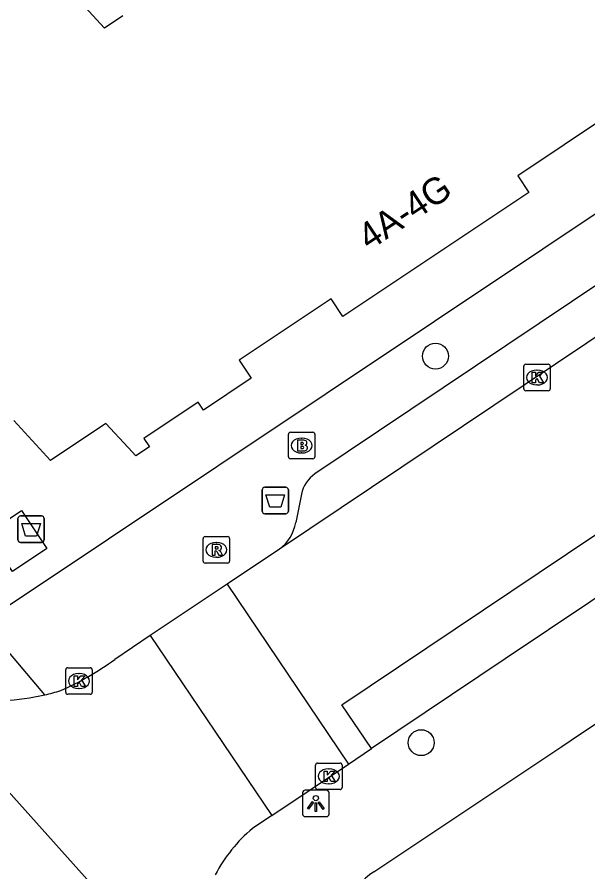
# Model space of a CAD drawing. Extents: x 161087 to 161922, y 382574 to 383873.
# Drawn here: x 161650.65 to 161672.22, y 382653.17 to 382685.44 of the extents above; entities that cross this region are included whole.
import ezdxf

# ---------------------------------------------------------------- set-up
doc = ezdxf.new("R2010")
doc.units = 0
for name, color, linetype in [('IMGEO_Afval_apart_plaats', 7, 'Continuous'), ('IMGEO_Afvalbak', 7, 'Continuous'), ('IMGEO_Boom', 7, 'Continuous'), ('IMGEO_Brandkraan', 7, 'Continuous'), ('IMGEO_Kolk', 7, 'Continuous'), ('IMGEO_Lichtpunt', 7, 'Continuous'), ('IMGEO_Pand', 7, 'Continuous'), ('IMGEO_Pand_nummerreeks', 7, 'Continuous'), ('IMGEO_Rijbaan_lokaal_gesloten', 7, 'Continuous'), ('IMGEO_Rijbaan_lokaal_open', 7, 'Continuous'), ('IMGEO_Rioolput', 7, 'Continuous'), ('IMGEO_Voetpad_gesloten', 7, 'Continuous'), ('IMGEO_Voetpad_open', 7, 'Continuous')]:
    doc.layers.add(name, color=color, linetype=linetype)

msp = doc.modelspace()

# ---------------------------------------------------------------- linework, layer by layer
at = {"layer": 'IMGEO_Afval_apart_plaats'}
for p, q in [((161650.686, 382665.711), (161650.686, 382666.511)), ((161650.686, 382666.511), (161650.686, 382665.711)), ((161650.786, 382666.611), (161651.576, 382666.611)), ((161651.576, 382666.611), (161650.786, 382666.611)), ((161651.676, 382666.511), (161651.676, 382665.711)), ((161651.676, 382665.711), (161651.676, 382666.511)), ((161651.576, 382665.611), (161650.786, 382665.611)), ((161650.786, 382665.611), (161651.576, 382665.611))]:
    msp.add_line(p, q, dxfattribs=at)
msp.add_lwpolyline([(161650.829, 382666.325), (161651.533, 382666.325), (161651.384, 382665.855), (161650.978, 382665.855), (161650.829, 382666.325)], dxfattribs=at)
for centre, start, end in [((161650.786, 382666.511), 90, 180), ((161650.786, 382666.511), 90, 180), ((161651.576, 382666.511), 0, 90), ((161651.576, 382666.511), 360, 90), ((161650.786, 382665.711), 180, 270), ((161650.786, 382665.711), 180, 270), ((161651.576, 382665.711), 270, 0), ((161651.576, 382665.711), 270, 0)]:
    msp.add_arc(centre, 0.1, start, end, dxfattribs=at)
at = {"layer": 'IMGEO_Afvalbak'}
for p, q in [((161659.915, 382666.795), (161659.915, 382667.595)), ((161659.915, 382667.595), (161659.915, 382666.795)), ((161660.015, 382667.695), (161660.805, 382667.695)), ((161660.805, 382667.695), (161660.015, 382667.695)), ((161660.905, 382667.595), (161660.905, 382666.795)), ((161660.905, 382666.795), (161660.905, 382667.595)), ((161660.805, 382666.695), (161660.015, 382666.695)), ((161660.015, 382666.695), (161660.805, 382666.695))]:
    msp.add_line(p, q, dxfattribs=at)
msp.add_lwpolyline([(161660.058, 382667.409), (161660.762, 382667.409), (161660.613, 382666.939), (161660.207, 382666.939), (161660.058, 382667.409)], dxfattribs=at)
for centre, start, end in [((161660.015, 382667.595), 90, 180), ((161660.015, 382667.595), 90, 180), ((161660.805, 382667.595), 0, 90), ((161660.805, 382667.595), 360, 90), ((161660.015, 382666.795), 180, 270), ((161660.015, 382666.795), 180, 270), ((161660.805, 382666.795), 270, 0), ((161660.805, 382666.795), 270, 0)]:
    msp.add_arc(centre, 0.1, start, end, dxfattribs=at)
at = {"layer": 'IMGEO_Boom'}
for centre in [(161666.46, 382672.645), (161665.922, 382658.053)]:
    msp.add_circle(centre, 0.489, dxfattribs=at)
at = {"layer": 'IMGEO_Brandkraan'}
for p, q in [((161660.98, 382669.77), (161661.832, 382669.77)), ((161660.905, 382668.844), (161660.905, 382669.696)), ((161661.393, 382669.55), (161661.418, 382669.55)), ((161661.906, 382669.696), (161661.906, 382668.844)), ((161661.832, 382668.77), (161660.98, 382668.77)), ((161661.416, 382668.99), (161661.391, 382668.99))]:
    msp.add_line(p, q, dxfattribs=at)
for points in [[(161660.98, 382669.77), (161661.832, 382669.77)], [(161660.905, 382668.844), (161660.905, 382669.696)], [(161661.253, 382669.47), (161661.253, 382669.07), (161661.466, 382669.07)], [(161661.484, 382669.47), (161661.253, 382669.47)], [(161661.906, 382669.696), (161661.906, 382668.844)], [(161661.432, 382669.389), (161661.378, 382669.389), (161661.378, 382669.313)], [(161661.378, 382669.313), (161661.431, 382669.313)], [(161661.44, 382669.237), (161661.378, 382669.237), (161661.378, 382669.156)], [(161661.378, 382669.156), (161661.44, 382669.156)], [(161661.832, 382668.77), (161660.98, 382668.77)]]:
    msp.add_lwpolyline(points, dxfattribs=at)
for centre, radius, start, end in [((161660.982, 382669.694), 0.0765, 91.552, 178.448), ((161660.982, 382669.694), 0.0765, 91.552, 178.448), ((161661.83, 382669.694), 0.0765, 1.552, 88.448), ((161661.83, 382669.694), 0.0765, 1.552, 88.448), ((161661.488, 382669.325), 0.145, 59.4692, 91.5367), ((161661.513, 382669.372), 0.0922, 285.5137, 58.1501), ((161661.433, 382669.351), 0.0379, 267.8285, 90.9355), ((161661.441, 382669.196), 0.0404, 269.8759, 90.5077), ((161661.518, 382669.18), 0.105, 301.3115, 78.989), ((161660.982, 382668.846), 0.0765, 181.552, 268.448), ((161660.982, 382668.846), 0.0765, 181.552, 268.448), ((161661.472, 382669.321), 0.251, 268.6676, 293.5347), ((161661.83, 382668.846), 0.0765, 271.552, 358.448), ((161661.83, 382668.846), 0.0765, 271.552, 358.448)]:
    msp.add_arc(centre, radius, start, end, dxfattribs=at)
for centre, major_axis, ratio, start_param, end_param in [((161661.392, 382669.27), (-0.387, 0.002), 0.722429, 4.712389, 7.853982), ((161661.417, 382669.27), (-0.39, 0.002), 0.717154, 1.570796, 4.712389)]:
    msp.add_ellipse(centre, major_axis=major_axis, ratio=ratio, start_param=start_param, end_param=end_param, dxfattribs=at)
at = {"layer": 'IMGEO_Kolk'}
for p, q in [((161669.871, 382672.338), (161670.723, 382672.338)), ((161669.796, 382671.412), (161669.796, 382672.264)), ((161670.284, 382672.118), (161670.309, 382672.118)), ((161670.797, 382672.264), (161670.797, 382671.412)), ((161670.307, 382671.558), (161670.282, 382671.558)), ((161670.723, 382671.338), (161669.871, 382671.338)), ((161652.491, 382659.954), (161652.491, 382660.806)), ((161652.566, 382660.88), (161653.418, 382660.88)), ((161653.492, 382660.806), (161653.492, 382659.954)), ((161652.979, 382660.66), (161653.004, 382660.66)), ((161653.002, 382660.1), (161652.977, 382660.1)), ((161653.418, 382659.88), (161652.566, 382659.88)), ((161661.929, 382656.357), (161661.929, 382657.209)), ((161662.004, 382657.283), (161662.856, 382657.283)), ((161662.93, 382657.209), (161662.93, 382656.357)), ((161662.417, 382657.063), (161662.442, 382657.063)), ((161662.856, 382656.283), (161662.004, 382656.283)), ((161662.44, 382656.503), (161662.415, 382656.503))]:
    msp.add_line(p, q, dxfattribs=at)
for points in [[(161669.871, 382672.338), (161670.723, 382672.338)], [(161669.796, 382671.412), (161669.796, 382672.264)], [(161670.117, 382672.038), (161670.24, 382672.038), (161670.24, 382671.887), (161670.37, 382672.038), (161670.534, 382672.038), (161670.388, 382671.887), (161670.541, 382671.638), (161670.389, 382671.638), (161670.304, 382671.802), (161670.24, 382671.735), (161670.24, 382671.638), (161670.117, 382671.638), (161670.117, 382672.038)], [(161670.797, 382672.264), (161670.797, 382671.412)], [(161670.723, 382671.338), (161669.871, 382671.338)], [(161652.491, 382659.954), (161652.491, 382660.806)], [(161652.566, 382660.88), (161653.418, 382660.88)], [(161653.492, 382660.806), (161653.492, 382659.954)], [(161652.812, 382660.58), (161652.935, 382660.58), (161652.935, 382660.429), (161653.065, 382660.58), (161653.229, 382660.58), (161653.083, 382660.429), (161653.236, 382660.18), (161653.084, 382660.18), (161652.999, 382660.344), (161652.935, 382660.277), (161652.935, 382660.18), (161652.812, 382660.18), (161652.812, 382660.58)], [(161653.418, 382659.88), (161652.566, 382659.88)], [(161661.929, 382656.357), (161661.929, 382657.209)], [(161662.004, 382657.283), (161662.856, 382657.283)], [(161662.93, 382657.209), (161662.93, 382656.357)], [(161662.25, 382656.983), (161662.373, 382656.983), (161662.373, 382656.832), (161662.503, 382656.983), (161662.667, 382656.983), (161662.521, 382656.832), (161662.674, 382656.583), (161662.522, 382656.583), (161662.437, 382656.747), (161662.373, 382656.68), (161662.373, 382656.583), (161662.25, 382656.583), (161662.25, 382656.983)], [(161662.856, 382656.283), (161662.004, 382656.283)]]:
    msp.add_lwpolyline(points, dxfattribs=at)
for centre, start, end in [((161669.873, 382672.262), 91.552, 178.448), ((161669.873, 382672.262), 91.552, 178.448), ((161670.721, 382672.262), 1.552, 88.448), ((161670.721, 382672.262), 1.552, 88.448), ((161669.873, 382671.414), 181.552, 268.448), ((161669.873, 382671.414), 181.552, 268.448), ((161670.721, 382671.414), 271.552, 358.448), ((161670.721, 382671.414), 271.552, 358.448), ((161652.568, 382660.804), 91.552, 178.448), ((161652.568, 382660.804), 91.552, 178.448), ((161653.416, 382660.804), 1.552, 88.448), ((161653.416, 382660.804), 1.552, 88.448), ((161652.568, 382659.956), 181.552, 268.448), ((161652.568, 382659.956), 181.552, 268.448), ((161653.416, 382659.956), 271.552, 358.448), ((161653.416, 382659.956), 271.552, 358.448), ((161662.006, 382657.207), 91.552, 178.448), ((161662.006, 382657.207), 91.552, 178.448), ((161662.854, 382657.207), 1.552, 88.448), ((161662.854, 382657.207), 1.552, 88.448), ((161662.006, 382656.359), 181.552, 268.448), ((161662.006, 382656.359), 181.552, 268.448), ((161662.854, 382656.359), 271.552, 358.448), ((161662.854, 382656.359), 271.552, 358.448)]:
    msp.add_arc(centre, 0.0765, start, end, dxfattribs=at)
for centre, major_axis, ratio, start_param, end_param in [((161670.283, 382671.838), (-0.387, 0.002), 0.722429, 4.712389, 7.853982), ((161670.308, 382671.838), (-0.39, 0.002), 0.717154, 1.570796, 4.712389), ((161652.978, 382660.38), (-0.387, 0.002), 0.722429, 4.712389, 7.853982), ((161653.003, 382660.38), (-0.39, 0.002), 0.717154, 1.570796, 4.712389), ((161662.416, 382656.783), (-0.387, 0.002), 0.722429, 4.712389, 7.853982), ((161662.441, 382656.783), (-0.39, 0.002), 0.717154, 1.570796, 4.712389)]:
    msp.add_ellipse(centre, major_axis=major_axis, ratio=ratio, start_param=start_param, end_param=end_param, dxfattribs=at)
at = {"layer": 'IMGEO_Lichtpunt'}
for p, q in [((161662.345, 382656.258), (161661.537, 382656.258)), ((161662.345, 382656.258), (161661.537, 382656.258)), ((161661.443, 382656.163), (161661.443, 382655.356)), ((161661.443, 382656.163), (161661.443, 382655.356)), ((161662.439, 382655.356), (161662.439, 382656.163)), ((161662.439, 382655.356), (161662.439, 382656.163)), ((161661.537, 382655.262), (161662.345, 382655.262)), ((161661.537, 382655.262), (161662.345, 382655.262))]:
    msp.add_line(p, q, dxfattribs=at)
for points in [[(161661.817, 382655.827), (161661.856, 382655.799), (161661.668, 382655.537), (161661.63, 382655.564), (161661.817, 382655.827)], [(161661.919, 382655.779), (161661.966, 382655.779), (161661.966, 382655.457), (161661.919, 382655.457), (161661.919, 382655.779)], [(161662.029, 382655.799), (161662.067, 382655.826), (161662.254, 382655.564), (161662.215, 382655.536), (161662.029, 382655.799)]]:
    msp.add_lwpolyline(points, dxfattribs=at)
msp.add_circle((161661.942, 382655.961), 0.0994, dxfattribs=at)
for centre, start, end in [((161661.537, 382656.163), 90, 180), ((161661.537, 382656.163), 90, 180), ((161662.345, 382656.163), 0, 90), ((161662.345, 382656.163), 0, 90), ((161661.537, 382655.356), 180, 270), ((161661.537, 382655.356), 180, 270), ((161662.345, 382655.356), 270, 0), ((161662.345, 382655.356), 270, 360)]:
    msp.add_arc(centre, 0.0946, start, end, dxfattribs=at)
at = {"layer": 'IMGEO_Pand'}
for points in [[(161654.648, 382685.492), (161653.956, 382685.031), (161647.175, 382692.39)], [(161680.47, 382685.832), (161673.485, 382681.175), (161673.077, 382681.786), (161669.572, 382679.45), (161669.988, 382678.826), (161662.965, 382674.144), (161662.524, 382674.806), (161659.048, 382672.489), (161659.499, 382671.812), (161657.692, 382670.607), (161657.496, 382670.901), (161655.445, 382669.534), (161655.654, 382669.221), (161655.143, 382668.881), (161654.854, 382669.193), (161654.012, 382670.104), (161651.92, 382668.71), (161650.536, 382670.209)]]:
    msp.add_lwpolyline(points, dxfattribs=at)
at = {"layer": 'IMGEO_Rijbaan_lokaal_gesloten'}
msp.add_lwpolyline([(161658.558, 382647.024), (161645.804, 382661.238)], dxfattribs=at)
at = {"layer": 'IMGEO_Rijbaan_lokaal_open'}
for points in [[(161699.988, 382691.772), (161660.57, 382665.356)], [(161664.046, 382657.83), (161662.924, 382659.486), (161675.735, 382668.065), (161680.939, 382671.625), (161685.938, 382675.035), (161686.973, 382675.729), (161688.094, 382674.073)], [(161660.57, 382665.356), (161658.586, 382664.031)], [(161658.586, 382664.031), (161655.686, 382662.094)], [(161658.586, 382664.031), (161663.174, 382657.246)], [(161655.686, 382662.094), (161654.342, 382661.196)], [(161655.686, 382662.094), (161660.282, 382655.309)], [(161663.174, 382657.246), (161664.046, 382657.83)], [(161660.282, 382655.309), (161663.174, 382657.246)], [(161660.282, 382655.309), (161659.549, 382654.818)]]:
    msp.add_lwpolyline(points, dxfattribs=at)
for centre, radius, start, end in [((161647.618, 382670.467), 11.453, 294.1911, 305.9528), ((161649.675, 382668.799), 9.166, 263.1686, 282.7798), ((161649.537, 382669.325), 9.71, 282.8883, 286.5988), ((161663.299, 382650.358), 5.827, 130.057, 152.2727)]:
    msp.add_arc(centre, radius, start, end, dxfattribs=at)
at = {"layer": 'IMGEO_Rioolput'}
for p, q in [((161657.682, 382664.906), (161657.682, 382665.758)), ((161657.757, 382665.832), (161658.609, 382665.832)), ((161658.17, 382665.612), (161658.195, 382665.612)), ((161658.683, 382665.758), (161658.683, 382664.906)), ((161658.193, 382665.052), (161658.168, 382665.052)), ((161658.609, 382664.832), (161657.757, 382664.832))]:
    msp.add_line(p, q, dxfattribs=at)
for points in [[(161657.682, 382664.906), (161657.682, 382665.758)], [(161657.757, 382665.832), (161658.609, 382665.832)], [(161658.683, 382665.758), (161658.683, 382664.906)], [(161658.271, 382665.53), (161658.019, 382665.532), (161658.019, 382665.132)], [(161658.019, 382665.132), (161658.143, 382665.132), (161658.143, 382665.294), (161658.154, 382665.294)], [(161658.197, 382665.451), (161658.143, 382665.451), (161658.143, 382665.37)], [(161658.143, 382665.37), (161658.195, 382665.37)], [(161658.201, 382665.265), (161658.272, 382665.132), (161658.412, 382665.132), (161658.347, 382665.258)], [(161658.609, 382664.832), (161657.757, 382664.832)]]:
    msp.add_lwpolyline(points, dxfattribs=at)
for centre, radius, start, end in [((161657.759, 382665.756), 0.0765, 91.552, 178.448), ((161657.759, 382665.756), 0.0765, 91.552, 178.448), ((161658.607, 382665.756), 0.0765, 1.552, 88.448), ((161658.607, 382665.756), 0.0765, 1.552, 88.448), ((161658.153, 382665.241), 0.0533, 26.0293, 88.6989), ((161658.179, 382665.559), 0.19, 274.7715, 282.9687), ((161658.203, 382665.355), 0.0964, 77.0061, 93.1865), ((161658.217, 382665.412), 0.0378, 276.6634, 79.6772), ((161658.27, 382665.42), 0.109, 350.3612, 89.416), ((161658.268, 382665.42), 0.112, 277.5842, 350.9817), ((161658.252, 382665.205), 0.108, 29.5134, 73.7905), ((161657.759, 382664.908), 0.0765, 181.552, 268.448), ((161657.759, 382664.908), 0.0765, 181.552, 268.448), ((161658.607, 382664.908), 0.0765, 271.552, 358.448), ((161658.607, 382664.908), 0.0765, 271.552, 358.448)]:
    msp.add_arc(centre, radius, start, end, dxfattribs=at)
for centre, major_axis, ratio, start_param, end_param in [((161658.169, 382665.332), (-0.387, 0.002), 0.722429, 4.712389, 7.853982), ((161658.194, 382665.332), (-0.39, 0.002), 0.717154, 1.570796, 4.712389)]:
    msp.add_ellipse(centre, major_axis=major_axis, ratio=ratio, start_param=start_param, end_param=end_param, dxfattribs=at)
at = {"layer": 'IMGEO_Voetpad_gesloten'}
msp.add_lwpolyline([(161651.78, 382665.38), (161650.485, 382664.516), (161649.527, 382665.952), (161650.822, 382666.816), (161651.78, 382665.38)], dxfattribs=at)
at = {"layer": 'IMGEO_Voetpad_open'}
for points in [[(161664.134, 382653.175), (161671.236, 382657.915), (161671.581, 382658.146), (161674.931, 382660.382), (161676.16, 382661.202), (161678.967, 382663.076), (161679.878, 382663.684), (161684.546, 382666.8), (161685.571, 382667.484), (161692.19, 382671.902), (161699.806, 382676.99), (161701.029, 382677.802), (161701.091, 382677.661), (161718.244, 382689.485), (161725.531, 382694.508), (161727.938, 382696.115), (161728.763, 382696.666), (161731.689, 382698.619), (161732.962, 382699.466), (161735.255, 382701.021)], [(161649.374, 382662.6), (161650.008, 382663.023), (161699.247, 382695.877)], [(161697.021, 382691.73), (161661.905, 382668.197)], [(161688.094, 382674.073), (161687.058, 382673.378), (161682.067, 382669.974), (161676.856, 382666.409), (161673.973, 382664.478), (161669.097, 382661.212), (161664.046, 382657.83)], [(161661.399, 382667.438), (161661.183, 382666.363)], [(161651.703, 382659.86), (161649.374, 382662.6)]]:
    msp.add_lwpolyline(points, dxfattribs=at)
for centre, radius, start, end in [((161662.572, 382667.204), 1.196, 123.8844, 168.7354), ((161659.601, 382666.636), 1.605, 307.1253, 350.2137), ((161666.296, 382650.037), 3.811, 124.568, 218.8673)]:
    msp.add_arc(centre, radius, start, end, dxfattribs=at)

# ---------------------------------------------------------------- texts
at = {"layer": 'IMGEO_Pand_nummerreeks'}
msp.add_text('4A-4G', height=1, rotation=33.6899, dxfattribs=at).set_placement((161663.96, 382676.61))

doc.saveas('drawing.dxf')
